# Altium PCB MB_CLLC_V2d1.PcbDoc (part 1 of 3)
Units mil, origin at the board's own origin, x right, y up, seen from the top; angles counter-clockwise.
Board outline 9000 x 7000 mil, 2 copper layers (Top Layer, Bottom Layer); 436 components, 223 nets, 1335 pads, 200 vias.
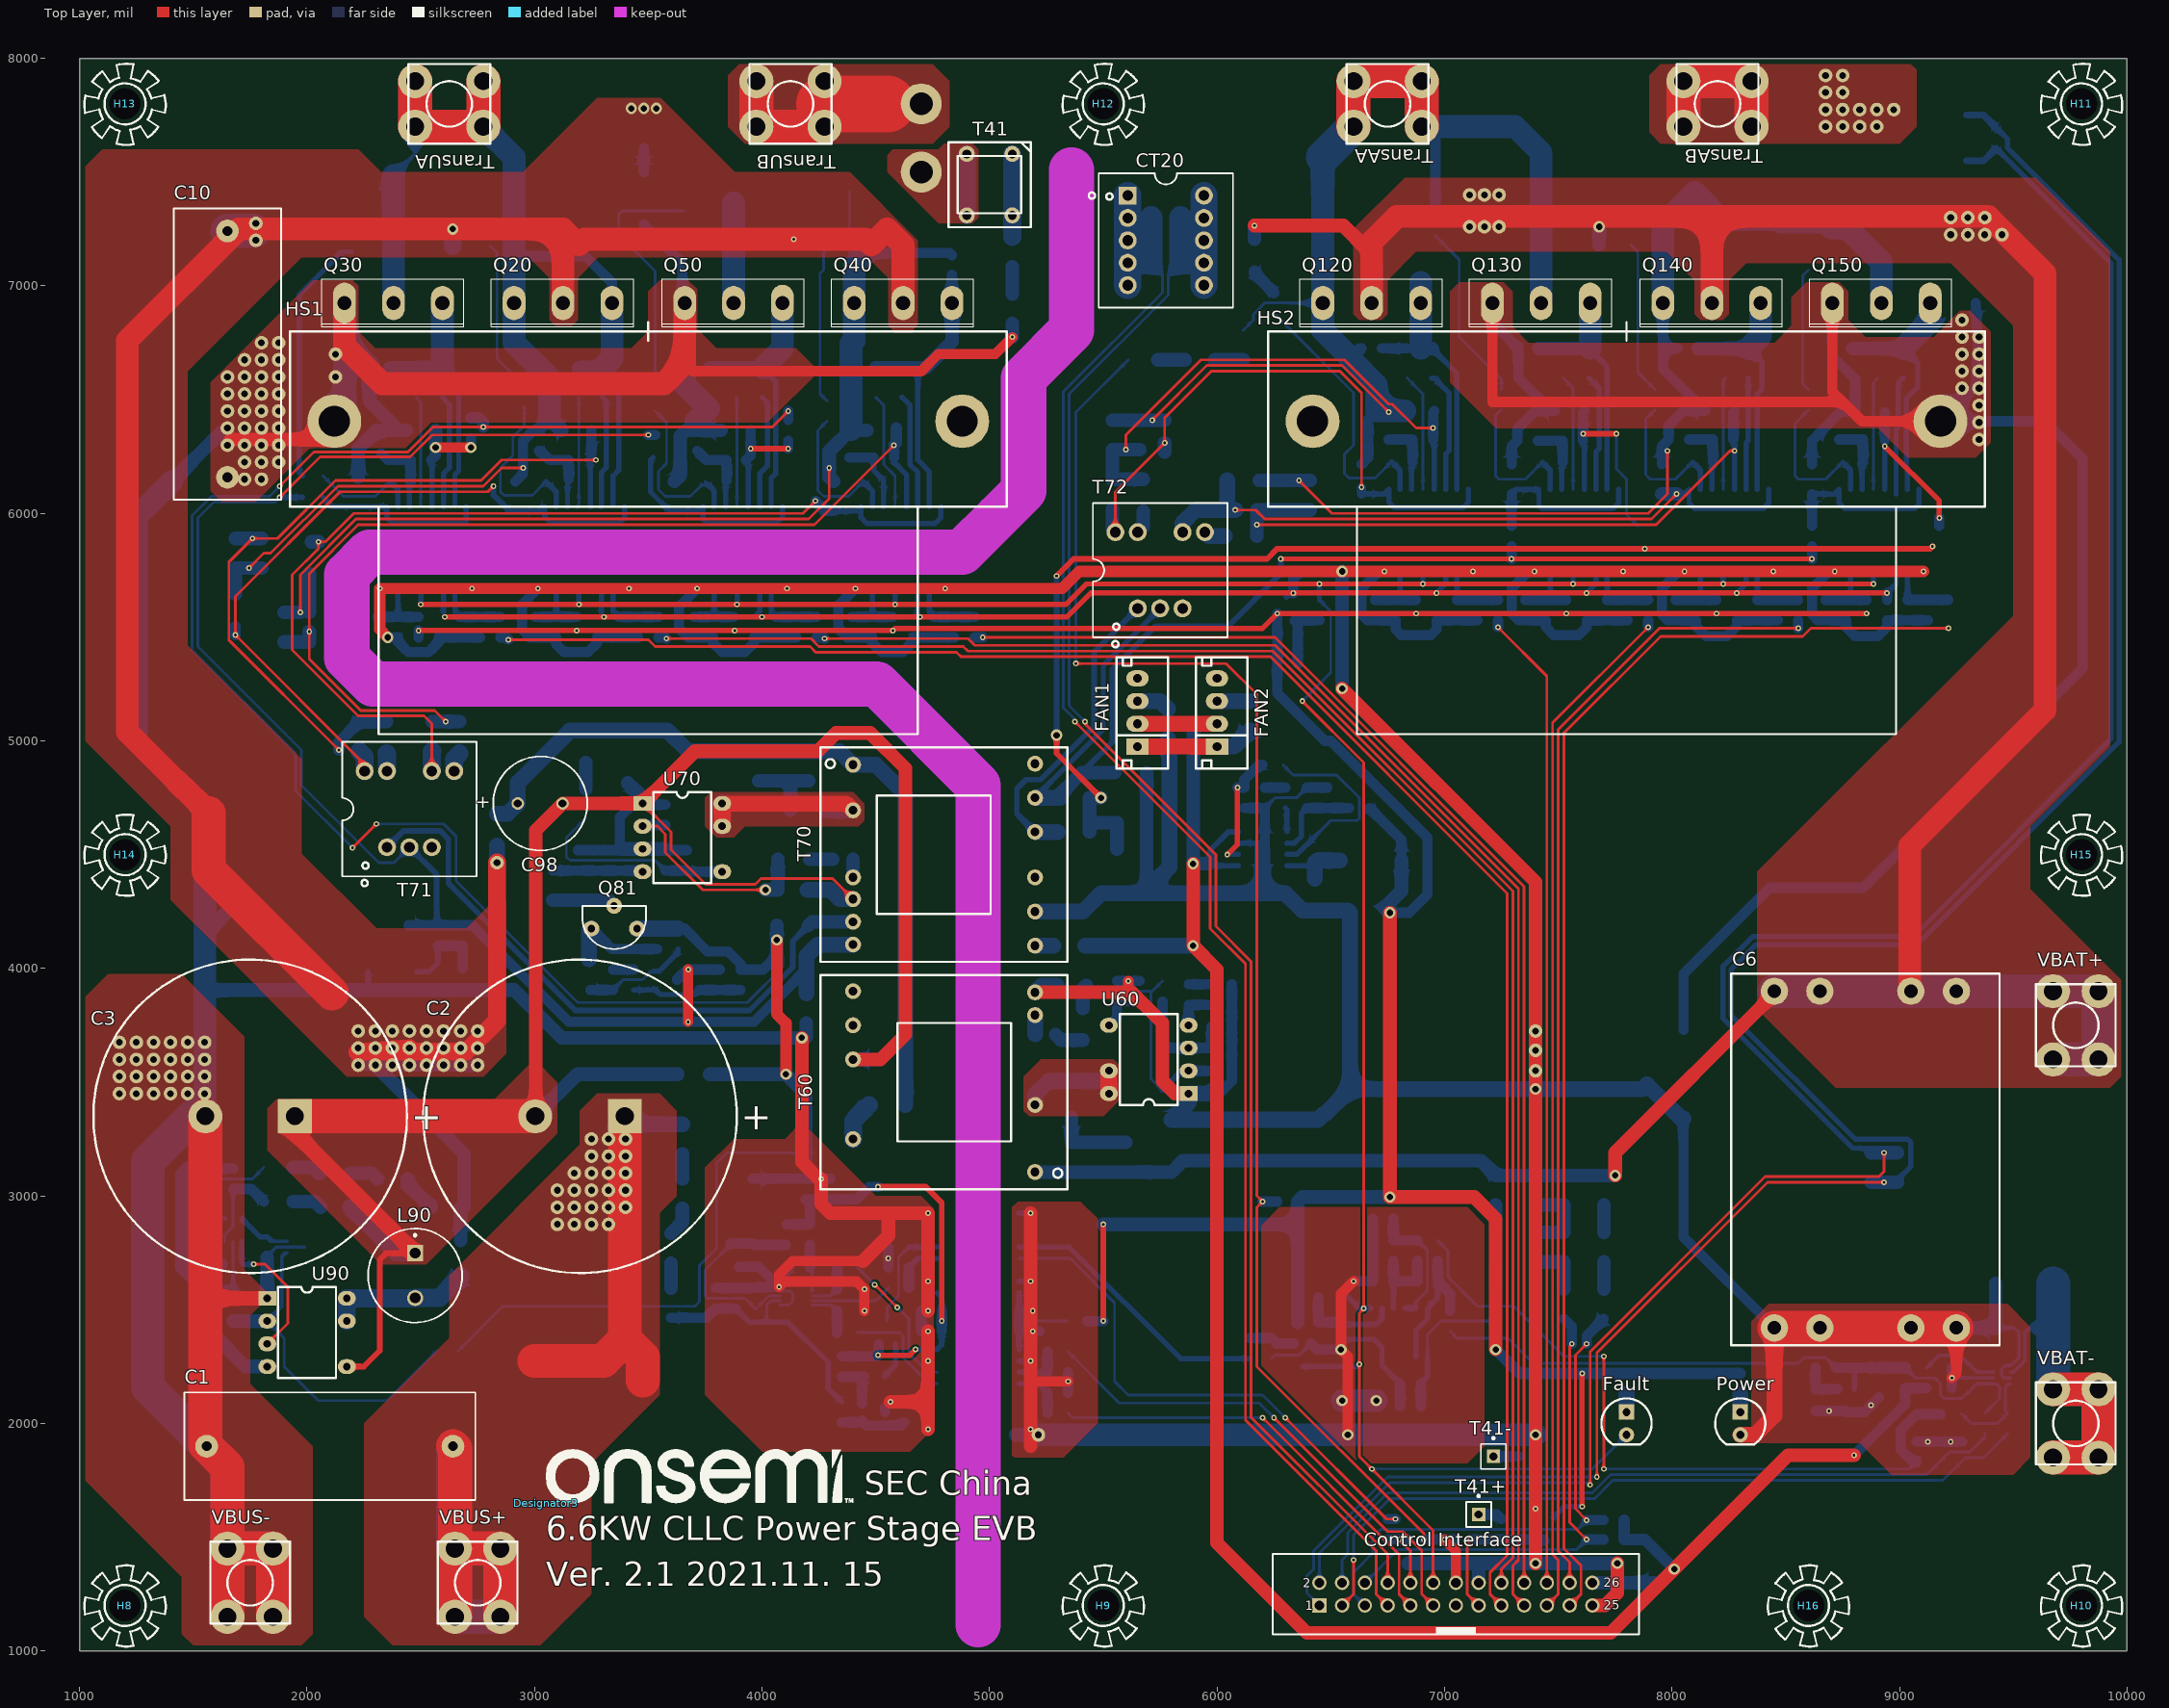
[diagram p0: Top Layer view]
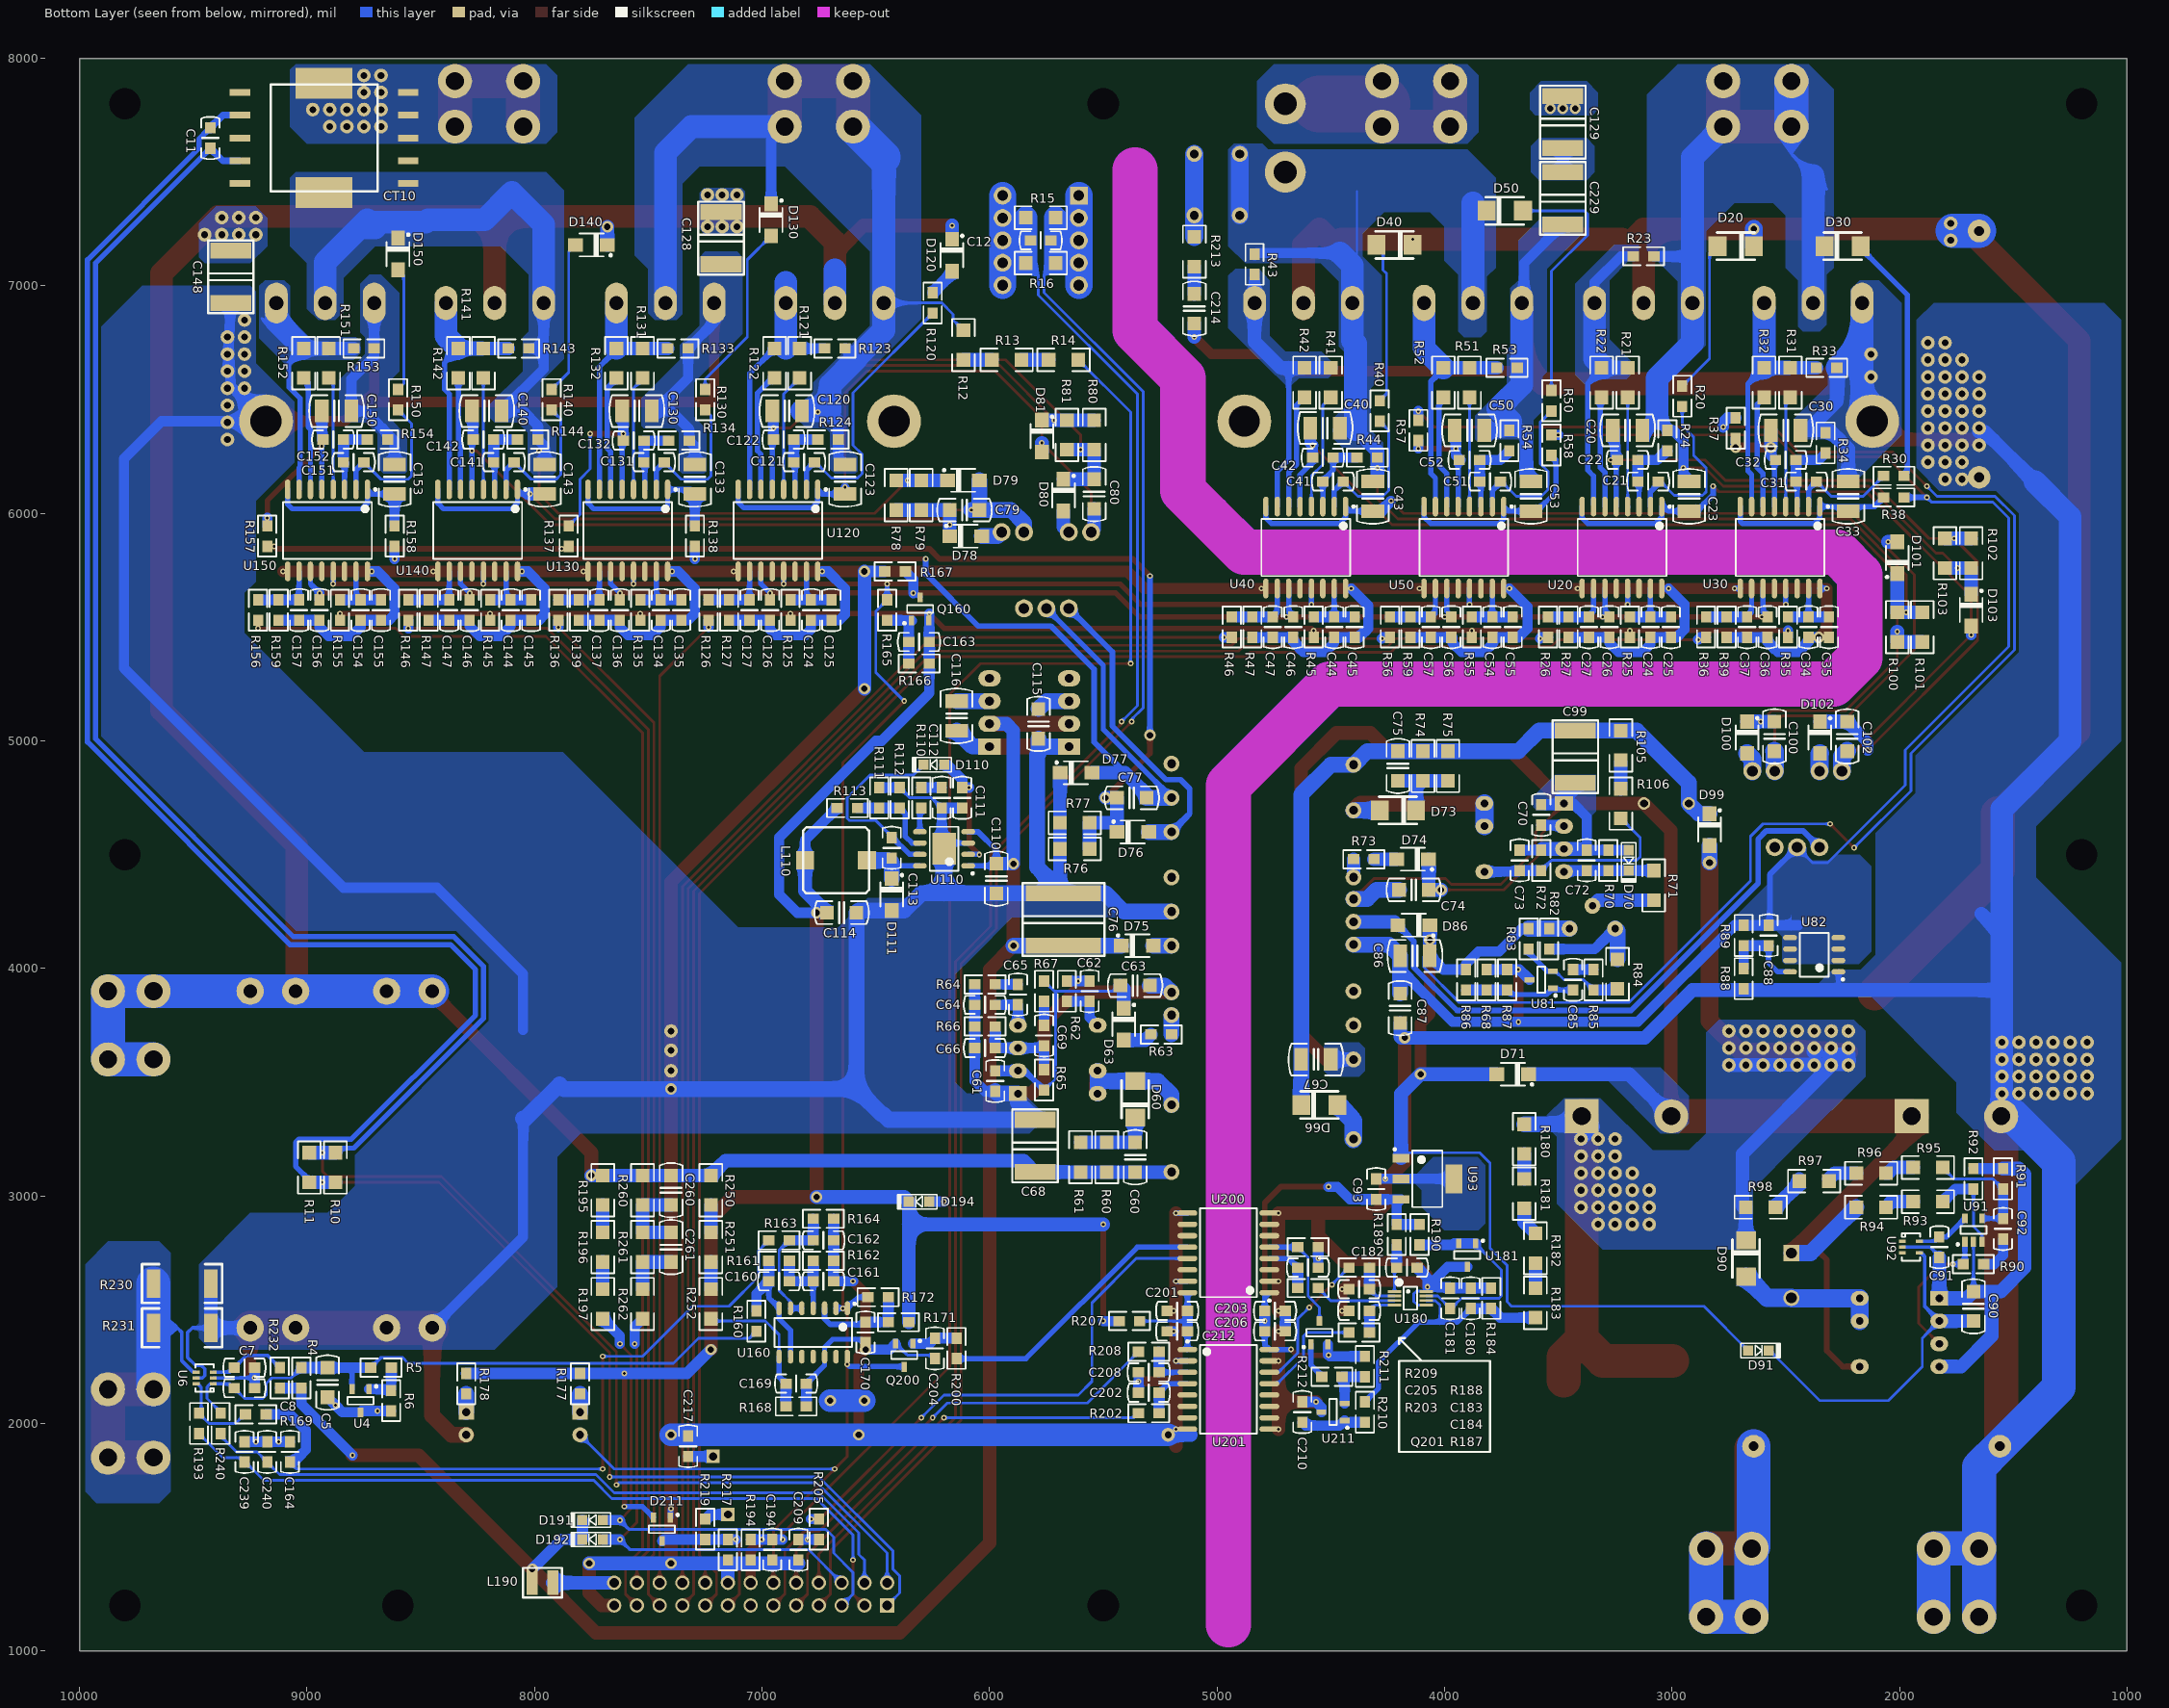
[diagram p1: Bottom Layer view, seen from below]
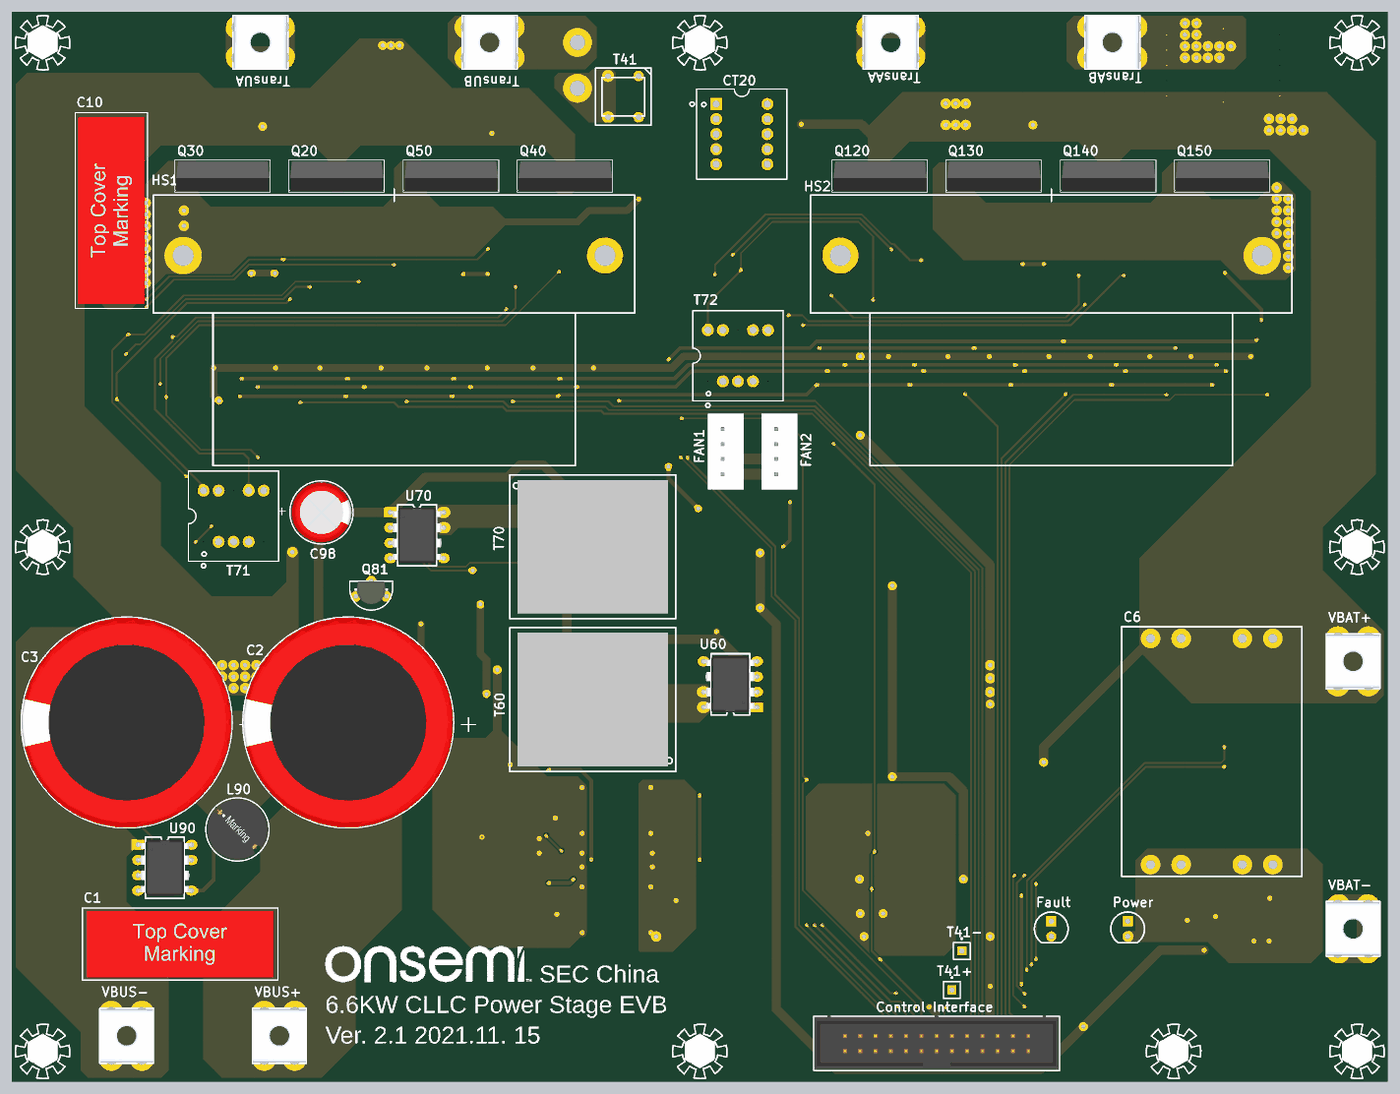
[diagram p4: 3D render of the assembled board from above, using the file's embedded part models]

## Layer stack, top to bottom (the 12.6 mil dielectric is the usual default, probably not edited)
Top Solder: solder mask 0.4, Solder Resist, Dk 3.5
Top Layer: signal copper 1.4
Dielectric 1: dielectric 12.6, FR-4, Dk 4.8
Bottom Layer: signal copper 1.4
Bottom Solder: solder mask 0.4, Solder Resist, Dk 3.5

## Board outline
1000,1000 1000,8000 10000,8000 10000,1000

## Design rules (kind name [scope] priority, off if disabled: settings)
Clearance [All] p1: gap=10 ignorepadtopadclearanceinfootprint=FALSE except(0: Arc-Hole Track-Hole SMDPad-Hole THPad-Hole Via-Hole Fill-Hole Poly-Hole Region-Hole Text-Hole)
PlaneConnect [All] p1: planeconnectstyle=Direct reliefexpansion=20 reliefentries=4 reliefconductorwidth=10 reliefairgap=10
PolygonConnect [All] p1: connectstyle=Direct reliefconductorwidth=10 reliefentries=4 polygonreliefangle="90 Angle" airgapwidth=10
RoutingVias [All] p1: holewidth=12 width=25 viastyle="Through Hole" minholewidth=12 minwidth=25 maxholewidth=28 maxwidth=50
SolderMaskExpansion [All] p1: expansion=4
Width [All] p1: maxlimit=250 minlimit=10 preferedwidth=45 minimp=50.000000 maximp=50.000000 favimp=50.000000
29 further rules are at their usual default settings.

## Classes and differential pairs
component class Sheet2_CLLC_V1d1: C1 C6 C7 C8 C10 C11 C12 C160 C161 C162 C163 C164 C169 C170 C180 C181 C182 C183 C184 C194 C201 C202 C203 C204 C205 C206 C208 C209 C210 C212 C214 C217 C239 C240 C260 C261 "Control Interface" CT10 CT20 D191 D192 D194 D211 Fault L190 Power Q160 Q180 Q200 Q201 R10 R11 R12 R13 R14 R15 R16 R160 R161 R162 R163 R164 R165 R166 R167 R168 R169 R171 R172 R177 R178 R180 R181 R182 R183 R184 R187 R188 R189 R190 R193 R194 R195 R196 R197 R200 R202 R203 R205 R207 R208 R209 R210 R211 R212 R213 R217 R219 R230 R231 R232 R240 R250 R251 R252 R260 R261 R262 T41 T41+ T41- U6 U160 U180 U181 U200 U201 U211 VBAT+ VBAT- VBUS+ VBUS-
component class Sheet1_CLLC_V1d1: C20 C21 C22 C23 C24 C25 C26 C27 C30 C31 C32 C33 C34 C35 C36 C37 C40 C41 C42 C43 C44 C45 C46 C47 C50 C51 C52 C53 C54 C55 C56 C57 C120 C121 C122 C123 C124 C125 C126 C127 C128 C129 C130 C131 C132 C133 C134 C135 C136 C137 C140 C141 C142 C143 C144 C145 C146 C147 C148 C150 C151 C152 C153 C154 C155 C156 C157 C229 D20 D30 D40 D50 D120 D130 D140 D150 Q20 Q30 Q40 Q50 Q120 Q130 Q140 Q150 R20 R21 R22 R23 R24 R25 R26 R27 R30 R31 R32 R33 R34 R35 R36 R37 R38 R39 R40 R41 R42 R43 R44 R45 R46 R47 R50 R51 R52 R53 R54 R55 R56 R57 R58 R59 R120 R121 R122 R123 R124 R125 R126 R127 R130 R131 R132 R133 R134 R135 R136 R137 R138 R139 R140 R141 R142 R143 R144 R145 R146 R147 R150 R151 R152 R153 R154 R155 R156 R157 R158 R159 TransAA TransAB TransUA TransUB U20 U30 U40 U50 U120 U130 U140 U150
component class Auxiliary_Power: C2 C3 C5 C60 C61 C62 C63 C64 C65 C66 C67 C68 C69 C70 C72 C73 C74 C75 C76 C77 C79 C80 C85 C86 C87 C88 C90 C91 C92 C93 C98 C99 C100 C102 C110 C111 C112 C113 C114 C115 C116 D60 D63 D66 D70 D71 D73 D74 D75 D76 D77 D78 D79 D80 D81 D86 D90 D91 D99 D100 D101 D102 D103 D110 D111 FAN1 FAN2 L90 L110 Q81 R4 R5 R6 R60 R61 R62 R63 R64 R65 R66 R67 R68 R70 R71 R72 R73 R74 R75 R76 R77 R78 R79 R80 R81 R82 R83 R84 R85 R86 R87 R88 R89 R90 R91 R92 R93 R94 R95 R96 R97 R98 R100 R101 R102 R103 R105 R106 R110 R111 R112 R113 T60 T70 T71 T72 U4 U60 U70 U81 U82 U90 U91 U92 U93 U110

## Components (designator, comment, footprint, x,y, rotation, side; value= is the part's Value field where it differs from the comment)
C1 "470nF, 1000V" L31_W11_H20_P27.5 2100,1900 r0 top locked
C2 "680uF/450V" WCAP-AI3H_35x57 3200,3350 r0 top locked
C3 "680uF/450V" WCAP-AI3H_35x57 1750,3350 r0 top locked
C5 "106" SMT_1206_CM 8910,2180 r90 bottom
C6 "30uF/800V" CAP-FILM_EZPE_41X30A 8850,3160 r270 top locked
C7 "104" SMT_0805_CM 9275,2245 r0 bottom
C8 "104" SMT_0805_CM 9275,2155 r0 bottom
C10 "470nF, 1000V" L31_W11_H20_P27.5 1650,6700 r90 top locked
C11 "101" SMT_0805_CM 9425,7650 r90 bottom
C12 "101" SMT_0805_CM 5775,7200 r180 bottom
C20 "226" SMT_1210 3195,6365 r180 bottom
C21 "101" SMT_0805_CM 3105,6140 r180 bottom
C22 "105" SMT_0805_CM 3195,6235 r180 bottom
C23 "226" SMT_1210 2925,6075 r90 bottom locked
C24 "104" SMT_0805_CM 3095,5500 r90 bottom
C25 "225" SMT_0805_CM 3005,5500 r90 bottom
C26 "101" SMT_0805_CM 3275,5500 r270 bottom
C27 "101" SMT_0805_CM 3365,5500 r90 bottom
C30 "226" SMT_1210 2500,6365 r180 bottom
C31 "101" SMT_0805_CM 2410,6140 r180 bottom
C32 "105" SMT_0805_CM 2500,6235 r180 bottom
C33 "226" SMT_1210 2225,6075 r90 bottom
C34 "104" SMT_0805_CM 2400,5500 r90 bottom
C35 "225" SMT_0805_CM 2310,5500 r90 bottom
C36 "101" SMT_0805_CM 2580,5500 r270 bottom
C37 "101" SMT_0805_CM 2670,5500 r90 bottom
C40 "226" SMT_1210 4525,6375 r180 bottom
C41 "101" SMT_0805_CM 4490,6140 r180 bottom
C42 "105" SMT_0805_CM 4535,6245 r180 bottom
C43 "226" SMT_1210 4315,6075 r90 bottom
C44 "104" SMT_0805_CM 4485,5500 r90 bottom
C45 "225" SMT_0805_CM 4395,5500 r90 bottom
C46 "101" SMT_0805_CM 4665,5500 r270 bottom
C47 "101" SMT_0805_CM 4755,5500 r90 bottom
C50 "226" SMT_1210 3890,6365 r180 bottom
C51 "101" SMT_0805_CM 3800,6140 r180 bottom
C52 "105" SMT_0805_CM 3890,6235 r180 bottom locked
C53 "226" SMT_1210 3620,6075 r90 bottom
C54 "104" SMT_0805_CM 3790,5500 r90 bottom
C55 "225" SMT_0805_CM 3700,5500 r90 bottom
C56 "101" SMT_0805_CM 3970,5500 r270 bottom
C57 "101" SMT_0805_CM 4060,5500 r90 bottom
C60 "222/630V" SMT_1206_CM 5360,3170 r270 bottom
C61 "104" SMT_0805_CM 5975,3505 r90 bottom
C62 "102" SMT_0805_CM 5560,3900 r270 bottom
C63 "104/1206" SMT_1206_CM 5360,3925 r0 bottom
C64 "471" SMT_0805_CM 6020,3840 r180 bottom
C65 "223" SMT_0805_CM 5875,3885 r270 bottom
C66 "102" SMT_0805_CM 6020,3650 r180 bottom
C67 "154" SMT_1210 4565,3600 r0 bottom
C68 "105/630V" CAP2220 5800,3220 r270 bottom
C69 "223" SMT_0805_CM 5760,3705 r270 bottom
C70 "104" SMT_0805_CM 3575,4675 r270 bottom
C72 "102" SMT_0805_CM 3375,4475 r270 bottom
C73 "102" SMT_0805_CM 3670,4475 r270 bottom
C74 "106" SMT_1206_CM 4135,4345 r180 bottom
C75 "222/630V" SMT_1206_CM 4205,4890 r90 bottom
C76 "25V/157" CAP2220_3 5675,4215 r90 bottom
C77 "106" SMT_1206_CM 5375,4750 r0 bottom
C79 "106" SMT_1206_CM 6110,6015 r0 bottom
C80 "106" SMT_1206_CM 5540,6085 r90 bottom
C85 "223" SMT_0805_CM 3435,3950 r90 bottom
C86 "226" SMT_1210 4130,4055 r180 bottom
C87 "106" SMT_1206_CM 4195,3825 r270 bottom
C88 "102" SMT_0805_CM 2575,4145 r270 bottom
C90 "106" SMT_1206_CM 1675,2515 r270 bottom
C91 "105" SMT_0805_CM 1825,2775 r90 bottom
C92 "104" SMT_0805_CM 1545,2855 r90 bottom
C93 "105" SMT_0805_CM 4300,3030 r270 bottom
C98 "NC" WCAP-ATG5_10x25 3025,4725 r180 top locked
C99 "105/630V" CAP2220 3425,4930 r90 bottom locked
C100 "475" SMT_1206_CM 2550,5020 r90 bottom
C102 "475" SMT_1206_CM 2230,5020 r90 bottom
C110 "106" SMT_1206_CM 5970,4395 r90 bottom
C111 "104" SMT_0805_CM 6120,4750 r90 bottom
C112 "222" SMT_0805_CM 6210,4750 r90 bottom
C113 "104" SMT_0805_CM 6430,4530 r270 bottom
C114 "106" SMT_1206_CM 6650,4245 r0 bottom
C115 "106" SMT_1206_CM 5785,5075 r90 bottom
C116 "226" SMT_1210 6145,5110 r90 bottom
C120 "226" SMT_1210 6890,6450 r180 bottom
C121 "101" SMT_0805_CM 6815,6225 r180 bottom
C122 "105" SMT_0805_CM 6905,6325 r180 bottom
C123 "226" SMT_1210 6635,6150 r90 bottom locked
C124 "104" SMT_0805_CM 6785,5575 r90 bottom
C125 "225" SMT_0805_CM 6695,5575 r90 bottom
C126 "101" SMT_0805_CM 6965,5575 r270 bottom
C127 "101" SMT_0805_CM 7055,5575 r90 bottom
C128 "105/630V" CAP2220 7180,7210 r90 bottom
C129 "105/630V" CAP2220 3480,7720 r90 bottom
C130 "226" SMT_1210 7550,6450 r180 bottom
C131 "101" SMT_0805_CM 7475,6225 r180 bottom
C132 "105" SMT_0805_CM 7564,6320 r180 bottom
C133 "226" SMT_1210 7295,6150 r90 bottom
C134 "104" SMT_0805_CM 7445,5575 r90 bottom
C135 "225" SMT_0805_CM 7355,5575 r90 bottom
C136 "101" SMT_0805_CM 7625,5575 r270 bottom
C137 "101" SMT_0805_CM 7715,5575 r90 bottom
C140 "226" SMT_1210 8210,6450 r180 bottom
C141 "101" SMT_0805_CM 8135,6225 r180 bottom
C142 "105" SMT_0805_CM 8225,6325 r180 bottom
C143 "226" SMT_1210 7955,6150 r90 bottom
C144 "104" SMT_0805_CM 8105,5575 r90 bottom
C145 "225" SMT_0805_CM 8015,5575 r90 bottom
C146 "101" SMT_0805_CM 8285,5575 r270 bottom
C147 "101" SMT_0805_CM 8375,5575 r90 bottom
C148 "105/630V" CAP2220 9335,7040 r90 bottom
C150 "226" SMT_1210 8870,6450 r180 bottom
C151 "101" SMT_0805_CM 8795,6225 r180 bottom
C152 "105" SMT_0805_CM 8885,6325 r180 bottom
C153 "226" SMT_1210 8615,6150 r90 bottom locked
C154 "104" SMT_0805_CM 8765,5575 r90 bottom
C155 "225" SMT_0805_CM 8675,5575 r90 bottom
C156 "101" SMT_0805_CM 8945,5575 r270 bottom
C157 "101" SMT_0805_CM 9035,5575 r90 bottom
C160 "104" SMT_0805_CM 6925,2625 r0 bottom
C161 "104" SMT_0805_CM 6730,2625 r0 bottom
C162 "104" SMT_0805_CM 6730,2805 r0 bottom
C163 "471" SMT_0805_CM 6310,5435 r180 bottom
C164 "102" SMT_0805_CM 9075,1875 r270 bottom
C169 "102" SMT_0805_CM 6850,2175 r0 bottom
C170 "104" SMT_0805_CM 6545,2400 r90 bottom
C180 "101" SMT_0805_CM 3885,2550 r270 bottom
C181 "104" SMT_0805_CM 3975,2550 r270 bottom
C182 "104" SMT_0805_CM 4165,2685 r0 bottom
C183 "101" SMT_0805_CM 4375,2590 r180 bottom
C184 "101" SMT_0805_CM 4375,2495 r180 bottom
C194 "NC" SMT_0805_CM 6955,1445 r90 bottom
C201 "105" SMT_0805_CM 5175,2495 r180 bottom
C202 "101" SMT_0805_CM 5300,2135 r180 bottom
C203 "104" SMT_0805_CM 4745,2495 r0 bottom
C204 "102" SMT_0805_CM 6240,2330 r90 bottom
C205 "101" SMT_0805_CM 4600,2685 r0 bottom
C206 "105" SMT_0805_CM 4745,2405 r0 bottom
C208 "101" SMT_0805_CM 5300,2225 r180 bottom
C209 "NC" SMT_0805_CM 6840,1445 r90 bottom
C210 "101" SMT_0805_CM 4625,2050 r270 bottom
C212 "104" SMT_0805_CM 5175,2405 r180 bottom
C214 "222/630V" SMT_1206_CM 5100,6900 r90 bottom
C217 "104" SMT_0805_CM 7325,1900 r270 bottom
C229 "105/630V" CAP2220 3480,7385 r90 bottom
C239 "102" SMT_0805_CM 9275,1875 r270 bottom
C240 "102" SMT_0805_CM 9175,1875 r270 bottom
C260 "222/630V" SMT_1206_CM 7400,3025 r90 bottom
C261 "222/630V" SMT_1206_CM 7400,2775 r90 bottom
"Control Interface" "61202621621" 61202621621 7050,1250 r0 top locked
CT10 "WE_750316796" CT_EE13 8925,7650 r180 bottom locked
CT20 "WE_750344930" Trans_EE13_6_6_10Pin_V#1 5775,7200 r0 top locked
D20 "NRVUS2MA" DO-214AC(SMA) 2720,7175 r180 bottom
D30 "NRVUS2MA" DO-214AC(SMA) 2250,7175 r0 bottom
D40 "NRVUS2MA" DO-214AC(SMA) 4220,7180 r180 bottom locked
D50 "NRVUS2MA" DO-214AC(SMA) 3735,7330 r0 bottom
D60 "NRVA4007T3G" DO-214AC(SMA) 5360,3425 r270 bottom
D63 "NRVHPRS1BFA" SOD-123FL 5410,3755 r270 bottom
D66 "NRVUS2MA" DO-214AC(SMA) 4550,3400 r0 bottom
D70 "BAS16H" SOD-323M 3190,4520 r270 bottom
D71 "NRVUS1JFA" SOD-123FL 3700,3535 r0 bottom
D73 "NRVA4007T3G" DO-214AC(SMA) 4205,4695 r180 bottom
D74 "NRVHPRS1BFA" SOD-123FL 4140,4480 r0 bottom
D75 "NRVBSS36FA" SOD-123FL 5350,4100 r180 bottom
D76 "NRVBS215FA" SOD-123FL 5370,4600 r180 bottom
D77 "MMSZ4V7T1G" SOD-123FL 5620,4860 r180 bottom
D78 "NRVBS215FA" SOD-123FL 6105,5900 r180 bottom
D79 "MMSZ4V7T1G" SOD-123FL 6115,6145 r180 bottom
D80 "NRVBS215FA" SOD-123FL 5675,6080 r270 bottom
D81 "MMSZ4V7T1G" SOD-123FL 5770,6340 r270 bottom
D86 "NRVBS215FA" SOD-123FL 4135,4190 r0 bottom
D90 "NRVUS2MA" DO-214AC(SMA) 2675,2725 r90 bottom
D91 "BAS16H" SOD-323M 2665,2320 r180 bottom
D99 "NRVUS1JFA" SOD-123FL 2835,4610 r270 bottom
D100 "NRVBS215FA" SOD-123FL 2670,5015 r270 bottom
D101 "MMSZ4V7T1G" SOD-123FL 2010,5805 r90 bottom
D102 "NRVBS215FA" SOD-123FL 2350,5015 r270 bottom
D103 "MMSZ4V7T1G" SOD-123FL 1685,5575 r270 bottom
D110 "BAS16H" SOD-323M 6200,4895 r0 bottom
D111 "NRVB120VLSFT1G" SOD-123FL 6430,4325 r270 bottom
D120 "NRVUS1JFA" SOD-123FL 6165,7135 r270 bottom
D130 "NRVUS1JFA" SOD-123FL 6960,7290 r270 bottom
D140 "NRVUS1JFA" SOD-123FL 7750,7180 r0 bottom
D150 "NRVUS1JFA" SOD-123FL 8600,7140 r270 bottom
D191 "BAS16H" SOD-323M 7700,1575 r0 bottom
D192 "BAS16H" SOD-323M 7700,1490 r0 bottom
D194 "BAS16H" SOD-323M 6265,2975 r0 bottom
D211 "BAT54S" SOT-23-3L 7440,1535 r270 bottom
Designator3 "Comment" Logo 3050,1650 r0 top
FAN1 "" XH-4A 5650,4975 r90 top locked
FAN2 "" XH-4A 6000,4975 r90 top locked
Fault "Red" "LED 5MM-R" 7800,2000 r270 top locked
H8 "Comment" HOLE3.5-2 1200,1200 r0 top locked
H9 "Comment" HOLE3.5-2 5500,1200 r0 top locked
H10 "Comment" HOLE3.5-2 9800,1200 r0 top locked
H11 "Comment" HOLE3.5-2 9800,7800 r0 top locked
H12 "Comment" HOLE3.5-2 5500,7800 r0 top
H13 "Comment" HOLE3.5-2 1200,7800 r0 top locked
H14 "Comment" HOLE3.5-2 1200,4500 r0 top locked
H15 "Comment" HOLE3.5-2 9800,4500 r0 top locked
H16 "Comment" HOLE3.5-2 8600,1200 r0 top locked
HS1 "Comment" Heatsink_80x60x20_with_25mm_FAN 3500,6800 r180 top locked
HS2 "Comment" Heatsink_80x60x20_with_25mm_FAN 7800,6800 r180 top locked
L90 "2200 uH, 0.48 A" WE-TI_1014_Standard 2475,2650 r270 top
L110 "22uH" INDUCTOR-7*7*3.5 6675,4475 r0 bottom
L190 "100uH" Bead_1210 7965,1300 r0 bottom
Power "Green" "LED 5MM-R" 8300,2000 r270 top locked
Q20 "NVHL040N120SC1" TO247#1 3125,6925 r180 top locked
Q30 "NVHL040N120SC1" TO247#2 2380,6925 r180 top locked
Q40 "NVHL040N120SC1" TO247#1 4620,6925 r180 top locked
Q50 "NVHL040N120SC1" TO247#3 3875,6925 r180 top locked
Q81 "FQN1N60CTA" TO92a 3350,4225 r180 top
Q120 "NVHL020N090SC1" TO247#1 6680,6925 r180 top locked
Q130 "NVHL020N090SC1" TO247#4 7425,6925 r180 top locked
Q140 "NVHL020N090SC1" TO247#1 8175,6925 r180 top locked
Q150 "NVHL020N090SC1" TO247#4 8920,6925 r180 top locked
Q160 "SMMBT2907ALT1G" SOT-23-3L 6305,5580 r90 bottom
Q200 "SMMBT4401LT1G" SOT-23-3L 6375,2300 r270 bottom
Q201 "SMMBT2907ALT1G" SOT-23-3L 4550,2398.82 r90 bottom
R4 "2.2K" SMT_0805_RM 9025,2200 r90 bottom
R5 "6.65K" SMT_0805_RM 8675,2245 r180 bottom
R6 "4.75K" SMT_0805_RM 8630,2100 r270 bottom
R10 "100" SMT_1206_RM 8875,3125 r270 bottom
R11 "100" SMT_1206_RM 8990,3125 r270 bottom
R12 "150K" SMT_1206_RM 6115,6740 r90 bottom
R13 "150K" SMT_1206_RM 5925,6675 r0 bottom
R14 "150K" SMT_1206_RM 5675,6675 r0 bottom
R15 "150" SMT_1206_RM 5775,7300 r180 bottom
R16 "150" SMT_1206_RM 5775,7100 r180 bottom
R20 "1K" SMT_0805_RM 2955,6515 r270 bottom
R21 "4.7" SMT_1206_RM 3195,6575 r90 bottom
R22 "4.7" SMT_1206_RM 3310,6575 r90 bottom locked
R23 "10K" SMT_0805_RM 3125,7130 r0 bottom locked
R24 "2.2" SMT_0805_RM 3020,6320 r270 bottom
R25 "4.7" SMT_0805_RM 3185,5500 r90 bottom
R26 "100" SMT_0805_RM 3545,5500 r270 bottom
R27 "2.2K" SMT_0805_RM 3455,5500 r270 bottom
R30 "1K" SMT_0805_RM 2025,6165 r0 bottom
R31 "4.7" SMT_1206_RM 2480,6575 r90 bottom
R32 "4.7" SMT_1206_RM 2595,6575 r90 bottom locked
R33 "10K" SMT_0805_RM 2320,6640 r0 bottom
R34 "2.2" SMT_0805_RM 2325,6310 r270 bottom
R35 "4.7" SMT_0805_RM 2490,5500 r90 bottom
R36 "100" SMT_0805_RM 2850,5500 r270 bottom
R37 "4.7" SMT_0805_RM 2720,6375 r270 bottom
R38 "4.7" SMT_0805_RM 2025,6070 r180 bottom
R39 "2.2K" SMT_0805_RM 2760,5500 r270 bottom
R40 "1K" SMT_0805_RM 4285,6450 r270 bottom
R41 "4.7" SMT_1206_RM 4500,6575 r90 bottom
R42 "4.7" SMT_1206_RM 4615,6575 r90 bottom
R43 "10K" SMT_0805_RM 4835,7095 r270 bottom
R44 "2.2" SMT_0805_RM 4340,6245 r0 bottom
R45 "4.7" SMT_0805_RM 4575,5500 r90 bottom
R46 "100" SMT_0805_RM 4935,5500 r270 bottom
R47 "2.2K" SMT_0805_RM 4845,5500 r270 bottom
R50 "1K" SMT_0805_RM 3530,6495 r270 bottom
R51 "4.7" SMT_1206_RM 3890,6575 r90 bottom
R52 "4.7" SMT_1206_RM 4005,6575 r90 bottom
R53 "10K" SMT_0805_RM 3725,6640 r0 bottom
R54 "2.2" SMT_0805_RM 3715,6320 r270 bottom
R55 "4.7" SMT_0805_RM 3880,5500 r90 bottom
R56 "100" SMT_0805_RM 4240,5500 r270 bottom
R57 "4.7" SMT_0805_RM 4115,6365 r270 bottom
R58 "4.7" SMT_0805_RM 3530,6300 r90 bottom
R59 "2.2K" SMT_0805_RM 4150,5500 r270 bottom
R60 "470K" SMT_1206_RM 5485,3170 r270 bottom
R61 "470K" SMT_1206_RM 5600,3170 r270 bottom
R62 "100K" SMT_0805_RM 5660,3900 r90 bottom
R63 "2.2" SMT_0805_RM 5245,3710 r0 bottom
R64 "10K" SMT_0805_RM 6020,3930 r0 bottom
R65 "220K" SMT_0805_RM 5760,3510 r90 bottom
R66 "43K" SMT_0805_RM 6020,3745 r0 bottom
R67 "43K" SMT_0805_RM 5760,3900 r270 bottom
R68 "56K" SMT_0805_RM 3815,3950 r90 bottom
R70 "100K" SMT_0805_RM 3280,4475 r90 bottom
R71 "47K" SMT_1206_RM 3080,4365 r90 bottom
R72 "20K" SMT_0805_RM 3575,4475 r90 bottom
R73 "2.2" SMT_0805_RM 4355,4480 r180 bottom
R74 "470K" SMT_1206_RM 4095,4890 r90 bottom
R75 "470K" SMT_1206_RM 3985,4890 r90 bottom
R76 "2.2K" SMT_1206_RM 5625,4525 r180 bottom
R77 "2.2K" SMT_1206_RM 5625,4640 r180 bottom
R78 "2.2K" SMT_1206_RM 6410,6080 r270 bottom
R79 "2.2K" SMT_1206_RM 6300,6080 r270 bottom
R80 "2.2K" SMT_1206_RM 5540,6345 r270 bottom
R81 "2.2K" SMT_1206_RM 5660,6345 r270 bottom
R82 "20K" SMT_0805_RM 3540,4130 r90 bottom
R83 "10K" SMT_0805_RM 3630,4130 r90 bottom
R84 "47K" SMT_1206_RM 3240,3975 r270 bottom
R85 "4.7K" SMT_0805_RM 3345,3950 r90 bottom
R86 "39K" SMT_0805_RM 3905,3950 r270 bottom
R87 "4.7K" SMT_0805_RM 3725,3950 r90 bottom
R88 "4.7K" SMT_0805_RM 2685,3955 r90 bottom
R89 "4.7K" SMT_0805_RM 2685,4145 r90 bottom
R90 "100K" SMT_0805_RM 1675,2700 r180 bottom
R91 "12.7K" SMT_0805_RM 1545,3075 r90 bottom
R92 "12.7K" SMT_0805_RM 1675,3075 r90 bottom
R93 "1M" SMT_1206_RM 1875,2975 r0 bottom
R94 "1M" SMT_1206_RM 2125,2950 r0 bottom
R95 "1M" SMT_1206_RM 1875,3125 r0 bottom
R96 "1M" SMT_1206_RM 2125,3100 r0 bottom
R97 "1M" SMT_1206_RM 2375,3065 r0 bottom
R98 "1M" SMT_1206_RM 2610,2950 r0 bottom
R100 "3.9K" SMT_1206_RM 2010,5500 r270 bottom
R101 "3.9K" SMT_1206_RM 1900,5500 r270 bottom
R102 "3.9K" SMT_1206_RM 1685,5825 r90 bottom
R103 "3.9K" SMT_1206_RM 1800,5825 r90 bottom
R105 "1M" SMT_1206_RM 3225,4980 r90 bottom
R106 "1M" SMT_1206_RM 3225,4725 r90 bottom
R110 "10K" SMT_0805_RM 6300,4750 r90 bottom
R111 "100" SMT_0805_RM 6485,4750 r90 bottom
R112 "2.2K" SMT_0805_RM 6395,4750 r90 bottom
R113 "300" SMT_0805_RM 6625,4705 r180 bottom
R120 "1K" SMT_0805_RM 6250,6925 r270 bottom
R121 "4.7" SMT_1206_RM 6835,6660 r90 bottom
R122 "4.7" SMT_1206_RM 6945,6660 r90 bottom
R123 "10K" SMT_0805_RM 6680,6725 r0 bottom
R124 "2.2" SMT_0805_RM 6710,6325 r0 bottom
R125 "4.7" SMT_0805_RM 6875,5575 r90 bottom
R126 "100" SMT_0805_RM 7235,5575 r270 bottom
R127 "2.2K" SMT_0805_RM 7145,5575 r270 bottom
R130 "1K" SMT_0805_RM 7250,6500 r270 bottom
R131 "4.7" SMT_1206_RM 7525,6660 r90 bottom
R132 "4.7" SMT_1206_RM 7640,6660 r90 bottom
R133 "10K" SMT_0805_RM 7370,6725 r0 bottom
R134 "2.2" SMT_0805_RM 7365,6320 r0 bottom
R135 "4.7" SMT_0805_RM 7535,5575 r90 bottom
R136 "100" SMT_0805_RM 7895,5575 r270 bottom
R137 "4.7" SMT_0805_RM 7850,5900 r90 bottom
R138 "4.7" SMT_0805_RM 7295,5900 r270 bottom
R139 "2.2K" SMT_0805_RM 7805,5575 r270 bottom
R140 "1K" SMT_0805_RM 7925,6500 r270 bottom
R141 "4.7" SMT_1206_RM 8225,6660 r90 bottom
R142 "4.7" SMT_1206_RM 8335,6660 r90 bottom
R143 "10K" SMT_0805_RM 8070,6725 r0 bottom
R144 "2.2" SMT_0805_RM 8030,6325 r0 bottom
R145 "4.7" SMT_0805_RM 8195,5575 r90 bottom
R146 "100" SMT_0805_RM 8555,5575 r270 bottom
R147 "2.2K" SMT_0805_RM 8465,5575 r270 bottom
R150 "1K" SMT_0805_RM 8600,6500 r270 bottom
R151 "4.7" SMT_1206_RM 8905,6660 r90 bottom
R152 "4.7" SMT_1206_RM 9015,6660 r90 bottom
R153 "10K" SMT_0805_RM 8750,6725 r0 bottom
R154 "2.2" SMT_0805_RM 8690,6325 r0 bottom
R155 "4.7" SMT_0805_RM 8855,5575 r90 bottom
R156 "100" SMT_0805_RM 9215,5575 r270 bottom
R157 "4.7" SMT_0805_RM 9175,5900 r90 bottom
R158 "4.7" SMT_0805_RM 8615,5900 r270 bottom
R159 "2.2K" SMT_0805_RM 9125,5575 r270 bottom
R160 "27K" SMT_0805_RM 7025,2450 r90 bottom
R161 "10K" SMT_0805_RM 6925,2715 r180 bottom
R162 "1.8K" SMT_0805_RM 6730,2715 r180 bottom
R163 "10K" SMT_0805_RM 6925,2805 r180 bottom
R164 "4.75K" SMT_0805_RM 6730,2900 r180 bottom
R165 "4.7K" SMT_0805_RM 6450,5575 r90 bottom
R166 "2.2K" SMT_0805_RM 6310,5340 r0 bottom
R167 "1K" SMT_0805_RM 6415,5745 r0 bottom
R168 "11.5K" SMT_0805_RM 6850,2075 r180 bottom
R169 "12K" SMT_0805_RM 9225,2040 r180 bottom
R171 "10" SMT_0805_RM 6400,2445 r0 bottom
R172 "2.2K" SMT_0805_RM 6490,2555 r0 bottom
R177 "330" SMT_0805_RM 7800,2175 r90 bottom
R178 "330" SMT_0805_RM 8300,2175 r270 bottom
R180 "1M" SMT_1206_RM 3650,3250 r90 bottom
R181 "1M" SMT_1206_RM 3650,3010 r90 bottom
R182 "1M" SMT_1206_RM 3600,2770 r90 bottom
R183 "1M" SMT_1206_RM 3600,2530 r90 bottom
R184 "12.7K" SMT_0805_RM 3795,2550 r90 bottom
R187 "100" SMT_0805_RM 4375,2400 r0 bottom
R188 "100" SMT_0805_RM 4375,2685 r0 bottom
R189 "10" SMT_0805_RM 4210,2830 r90 bottom
R190 "470" SMT_0805_RM 4110,2830 r270 bottom
R193 "2.2K" SMT_0805_RM 9475,2000 r270 bottom
R194 "NC" SMT_0805_RM 7050,1445 r270 bottom
R195 "1M" SMT_1206_RM 7700,3025 r90 bottom
R196 "1M" SMT_1206_RM 7700,2775 r90 bottom
R197 "1M" SMT_1206_RM 7700,2525 r90 bottom
R200 "1K" SMT_0805_RM 6145,2330 r90 bottom
R202 "100" SMT_0805_RM 5300,2045 r0 bottom
R203 "100" SMT_0805_RM 4600,2595 r0 bottom
R205 "100" SMT_0805_RM 6750,1535 r270 bottom
R207 "10" SMT_0805_RM 5385,2450 r0 bottom
R208 "100" SMT_0805_RM 5300,2315 r0 bottom
R209 "4.7K" SMT_0805_RM 4600,2775 r180 bottom
R210 "10K" SMT_0805_RM 4350,2050 r90 bottom
R211 "1K" SMT_0805_RM 4350,2250 r270 bottom
R212 "10K" SMT_0805_RM 4495,2205 r0 bottom
R213 "1K" SMT_1206_RM 5100,7150 r90 bottom
R217 "10K" SMT_0805_RM 7150,1445 r270 bottom
R219 "1K" SMT_0805_RM 7250,1535 r270 bottom
R230 "2mR" SMT_2512_R 9675,2615 r0 bottom
R231 "2mR" SMT_2512_R 9675,2420 r0 bottom
R232 "10" SMT_0805_RM 9120,2200 r90 bottom
R240 "2.2K" SMT_0805_RM 9380,2000 r270 bottom
R250 "1M" SMT_1206_RM 7225,3025 r90 bottom
R251 "1M" SMT_1206_RM 7225,2775 r90 bottom
R252 "1M" SMT_1206_RM 7225,2525 r90 bottom
R260 "3M" SMT_1206_RM 7525,3025 r90 bottom
R261 "3M" SMT_1206_RM 7525,2775 r90 bottom
R262 "3M" SMT_1206_RM 7525,2525 r90 bottom
T41 "EE8" EE8 5000,7445 r270 top locked
T41+ "" PIN1 7150,1600 r0 top
T41- "" PIN1 7215,1855 r0 top
T60 "PQ2016" Trans_PQ2016_14P#1 4800,3500 r180 top locked
T70 "PQ2016" Trans_PQ2016_14P#2 4800,4500 r0 top locked
T71 "EE13" Trans_EE13_6_6_10Pin_V#2 2450,4700 r90 top locked
T72 "EE13" Trans_EE13_6_6_10Pin_V#2 5750,5750 r90 top locked
TransAA "" TermL 6750,7800 r90 top
TransAB "" TermL 8200,7800 r90 top
TransUA "" TermL 2625,7800 r90 top
TransUB "" TermL 4125,7800 r90 top
U4 "SC431AVSNT1G" SOT-23-3L 8765,2100 r270 bottom
U6 "NCV210RSQT2G" SC70-6 9450,2200 r90 bottom
U20 "NCV57000DWR2G" SOP16W 3220,5850 r270 bottom locked
U30 "NCV57000DWR2G" SOP16W 2525,5850 r270 bottom locked
U40 "NCV57000DWR2G" SOP16W 4610,5850 r270 bottom locked
U50 "NCV57000DWR2G" SOP16W 3915,5850 r270 bottom locked
U60 "FSL538APG" DIP7 5700,3600 r180 top locked
U70 "FSL538APG" DIP7 3650,4575 r0 top locked
U81 "SC431AVSNT1G" SOT-23-3L 3575,3950 r0 bottom
U82 "NCV431AIDR2G" Sop8 2375,4060 r0 bottom locked
U90 "FSL4110LRN" DIP7 2000,2400 r0 top
U91 "NCV2003SN2T1G" SOT-23-5L 1675,2850 r90 bottom
U92 "NCV8715SQ33T2G" SC70-5 1950,2775 r270 bottom
U93 "NCV4274CST33T3G" SOT-223 4075,3075 r180 bottom locked
U110 "NCV890100PDR2G" SOIC8E 6200,4526 r0 bottom locked
U120 "NCV57000DWR2G" SOP16W 6930,5925 r270 bottom locked
U130 "NCV57000DWR2G" SOP16W 7590,5925 r270 bottom locked
U140 "NCV57000DWR2G" SOP16W 8250,5925 r270 bottom locked
U150 "NCV57000DWR2G" SOP16W 8910,5925 r270 bottom locked
U160 "NCV2901DR2G" SOP14 6800,2400 r270 bottom locked
U180 "NCD98010XMXTAG" SSOP8 4150,2550 r180 bottom locked
U181 "SC431AVSNT1G" SOT-23-3L 3900,2740 r270 bottom
U200 "NCID9401" SOP16W 4950,2750 r0 bottom locked
U201 "NCID9401" SOP16W 4950,2150 r180 bottom locked
U211 "SC431AVSNT1G" SOT-23-3L 4490,2050 r0 bottom
VBAT+ "" TermL 9775,3750 r0 top
VBAT- "" TermL 9775,2000 r0 top
VBUS+ "" TermL 2750,1300 r0 top
VBUS- "" TermL 1750,1300 r0 top

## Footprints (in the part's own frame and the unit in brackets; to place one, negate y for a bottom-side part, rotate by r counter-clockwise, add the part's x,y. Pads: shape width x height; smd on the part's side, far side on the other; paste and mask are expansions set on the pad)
61202621621 [mm] "26 pins, straight, gold plating"
  rect 1.6x1.6 hole 1.1: 1(-15.24,-1.27)
  round 1.6 hole 1.1: 2(-15.24,1.27) 3(-12.7,-1.27) 4(-12.7,1.27) 5(-10.16,-1.27) 6(-10.16,1.27) 7(-7.62,-1.27) 8(-7.62,1.27) 9(-5.08,-1.27) 10(-5.08,1.27) 11(-2.54,-1.27) 12(-2.54,1.27) 13(0,-1.27) 14(0,1.27) 15(2.54,-1.27) 16(2.54,1.27) 17(5.08,-1.27) 18(5.08,1.27) 19(7.62,-1.27) 20(7.62,1.27) 21(10.16,-1.27) 22(10.16,1.27) 23(12.7,-1.27) 24(12.7,1.27) 25(15.24,-1.27) 26(15.24,1.27)
  silkscreen extent -20.44,-4.5 20.44,4.5, body extent -20.34,-4.42 20.34,4.75, height 9.13
Bead_1210 [mil]
  rect 49x107 smd: 1(-45,0) 2(45,0)
  silkscreen extent -85,-65 85,65, body extent -63,-51 63,51, height 39
CAP2220 [mil]
  rect 70x180 smd: 1(-115,0) 2(115,0)
  silkscreen extent -160,-100 160,100, body extent -160,-100 160,100, height 200
CAP2220_3 [mil]
  rect 70x330 smd: 1(-115,0) 2(115,0)
  silkscreen extent -160,-180 160,180, body extent -160,-180 160,180, height 200
CAP-FILM_EZPE_41X30A [mil]
  round 120 / inner round 130 / far side round 120 hole 59: 1(-740,-200) 1(-740,200) 2(740,-200) 2(740,200)
  silkscreen extent -817,-590 817,590, body extent -815,-591 819,591, height 2008
CT_EE13 [mil]
  rect 90x30 / inner rect 0x0 / far side rect 0x0 all layers, no hole: 1(-370,200) 2(-370,100) 3(-370,0) 4(-370,-100) 5(-370,-200) 6(370,-200) 7(370,-100) 11(370,0) 11(370,100) 11(370,200)
  rect 250x135 / inner rect 0x0 / far side rect 0x0 all layers, no hole: 11(0,240) 12(0,-240)
  silkscreen extent -235,-235 235,235
DIP7 [mm]
  rect 2x1.65 hole 0.85: 1(-4.445,3.81)
  oval 2x1.65 hole 0.85: 2(-4.445,1.27) 3(-4.445,-1.27) 4(-4.445,-3.81) 5(4.445,-3.81) 6(4.445,1.27) 7(4.445,3.81)
  silkscreen extent -3.23,-5.08 3.23,5.08, body extent -4.59,-4.63 4.59,4.63, height 4.22
DO-214AC(SMA) [mm]
  rect 2x2.2 smd: 1(-2.032,0) 2(2.032,0)
  silkscreen extent -2.1,-1.53 2.1,1.53, body extent -2.3,-1.35 2.3,1.35, height 2.4
EE8 [mil]
  round 70 / inner round 110.24 / far side round 70 hole 39: 1(-135,100) 1(135,100) 2(-135,-100) 2(135,-100)
  silkscreen extent -188,-181 187,182, body extent -185,-181 189,181, height 394
Heatsink_80x60x20_with_25mm_FAN [mil]
  round 236.22 / inner round 80 / far side round 236.22 hole 137: 1(-1380,395) 2(1380,395)
  silkscreen extent -1575,-40 1575,1770, body extent -1570,0 1570,1770, height 2350
HOLE3.5-2 [mm]
  round 0 hole 3.5 unplated: 1(0,0)
  silkscreen extent -4.53,-4.58 4.54,4.47, body extent -2.49,-2.87 2.51,2.9
INDUCTOR-7*7*3.5 [mil]
  rect 80x80 smd: 1(-135.75,0) 2(135.75,0)
  silkscreen extent -145,-145 145,145, body extent -144,-144 144,144, height 130
L31_W11_H20_P27.5 [mm] "THT Film Capacitors, body 31x11mm"
  round 2.54 hole 1.1: 1(-13.75,0) 2(13.75,0)
  silkscreen extent -16.25,-6 16.25,6, body extent -15.5,-5.5 15.5,5.5, height 20.05
"LED 5MM-R" [mm] "红色5mm直插LED"
  rect 1.7x1.7 hole 0.9: 1(-1.27,0)
  round 1.7 hole 0.9: 2(1.27,0)
  silkscreen extent -2.8,-2.8 2.33,2.8, body extent -2.85,-2.85 2.45,2.85, height 8.75
Logo [mil] "onsemi"
  silkscreen extent 0,2 1350,236
PIN1 [mm] "Connector; Plug"
  rect 1.5x1.5 hole 0.9: 1(0,0)
  silkscreen extent -1.4,-1.4 1.4,2.17
SC70-5 [mil]
  rect 15x30 smd mask+0: 1(-26,-37.5) 2(0,-37.5) 3(26,-37.5) 4(26,37.5) 5(-26,37.5)
  silkscreen extent -60,-40 60,40, body extent -39,-41 39,41, height 40
SC70-6 [mil]
  rect 15x30 smd mask+0: 1(-26,-37.5) 2(0,-37.5) 3(26,-37.5) 4(26,37.5) 5(0,37.5) 6(-26,37.5)
  silkscreen extent -60,-40 60,40, body extent -39,-41 39,41, height 40
SMT_0805_CM [mil]
  rect 50x45 smd: 1(-45,0) 2(45,0)
  silkscreen extent -93,-40 93,40, body extent -39,-24 39,24, height 26
SMT_0805_RM [mil]
  rect 50x45 smd: 1(-45,0) 2(45,0)
  silkscreen extent -90,-40 90,40, body extent -39,-25 39,25, height 22
SMT_1206_CM [mil]
  rect 60x60 smd: 1(-65,0) 2(65,0)
  silkscreen extent -120,-50 120,50, body extent -63,-31 63,31, height 30
SMT_1206_RM [mil]
  rect 60x60 smd: 1(-65,0) 2(65,0)
  silkscreen extent -115,-50 115,50, body extent -63,-31 63,31, height 24
SMT_1210 [mil]
  rect 60x100 smd: 1(-65,0) 2(65,0)
  silkscreen extent -121,-70 121,70, body extent -63,-31 63,31, height 30
SMT_2512_R [mil]
  rect 60x125 smd: 1(0,0) 2(-251.97,0)
  silkscreen extent -302,-85 50,85, body extent -260,-65 8,65, height 25
SOD-123FL [mil]
  rect 65x60 smd: 1(70,0) 2(-70,0)
  silkscreen extent -90,-50 53,50, body extent -73,-31 73,31, height 47
SOD-323M [mil]
  rect 45x45 smd: 1(0,0) 2(90,0)
  silkscreen extent -33,-31 140,31, body extent 2,-24 100,26, height 35
SOIC8E [mm]
  oval 1.55x0.6 smd: 1(-2.7,1.905) 2(-2.7,0.635) 3(-2.7,-0.635) 4(-2.7,-1.905) 5(2.7,-1.905) 6(2.7,-0.635) 7(2.7,0.635) 8(2.7,1.905)
  rect 2.62x3.51 smd: 9(0,0)
  silkscreen extent -3.32,-2.45 1.6,2.87, body extent -3,-2.45 3,2.45, height 1.6
Sop8 [mm]
  oval 1.55x0.6 smd: 1(-2.7,1.905) 2(-2.7,-1.905) 2(-2.7,-0.635) 2(-2.7,0.635) 2(2.7,-1.905) 2(2.7,-0.635) 2(2.7,0.635) 8(2.7,1.905)
  silkscreen extent -3.32,-2.45 1.6,2.87, body extent -3,-2.45 3,2.45, height 1.6
SOP14 [mm]
  oval 1.55x0.6 smd: 1(-2.7,4.445) 2(-2.7,3.175) 3(-2.7,1.905) 4(-2.7,0.635) 5(-2.7,-0.635) 6(-2.7,-1.905) 7(-2.7,-3.175) 8(2.7,-3.175) 9(2.7,-1.905) 10(2.7,-0.635) 11(2.7,0.635) 12(2.7,1.905) 13(2.7,3.175) 14(2.7,4.445)
  silkscreen extent -3.32,-3.68 1.6,5.37, body extent -3,-5 3,5, height 1.6
SOP16W [mil]
  oval 87x23.62 smd: 1(-180,175) 2(-180,125) 3(-180,75) 4(-180,25) 5(-180,-25) 6(-180,-75) 7(-180,-125) 8(-180,-175) 9(180,-175) 10(180,-125) 11(180,-75) 12(180,-25) 13(180,25) 14(180,75) 15(180,125) 16(180,175)
  silkscreen extent -185,-195 125,215, body extent -118,-197 118,197, height 63
SOT-23-3L [mm]
  rect 1.1x0.6 smd: 1(-1.3,0.95) 2(-1.3,-0.95) 3(1.3,0)
  silkscreen extent -1.72,-1.45 0.43,1.87, body extent -1.4,-1.45 1.4,1.45, height 1.2
SOT-23-5L [mm]
  rect 1.1x0.6 smd: 1(-1.3,0.95) 2(-1.3,0) 3(-1.3,-0.95) 4(1.3,-0.95) 5(1.3,0.95)
  silkscreen extent -1.72,-1.45 0.43,1.88, body extent -1.4,-1.45 1.4,1.45, height 1.2
SOT-223 [mm]
  rect 1.9x0.95 smd: 1(-2.95,2.3) 2(-2.95,0) 3(-2.95,-2.3)
  rect 1.9x3.2 smd: 4(2.95,0)
  silkscreen extent -3.78,-3.15 1.68,3.42, body extent -3.43,-3.25 3.53,3.25, height 1.7
SSOP8 [mil]
  rect 60x11.8 smd: 1(-70,30) 2(-70,10) 3(-70,-10) 4(-70,-30) 5(70,-30) 6(70,-10) 7(70,10) 8(70,30)
  silkscreen extent -60,-50 30,80, body extent -118,-98 118,98, height 49
TermL [mil]
  round 150 / inner round 60 / far side round 150 hole 79: 1(-100,150) 1(-100,-150) 1(100,150) 1(100,-150)
  silkscreen extent -175,-180 175,180, body extent -173,-175 173,175, height 244
TO92a [mil]
  round 70 hole 32: 1(-100,50) 2(0,-50) 3(100,50)
  silkscreen extent -140,-50 140,140, body extent -112,-50 112,100, height 269
TO247#1 [mil]
  oval 100x150 hole 62: 1(-215,0) 2(0,0) 3(215,0)
  silkscreen extent -310,-105 315,105, body extent -305,-98 305,98, height 984
TO247#2 [mil]
  oval 100x150 hole 62: 1(-215,0) 2(0,0)
  oval 100x180 hole 62: 3(215,0)
  silkscreen extent -310,-105 315,105, body extent -305,-98 305,98, height 984
TO247#3 [mil]
  oval 100x160 hole 62: 1(-215,0)
  oval 100x150 hole 62: 2(0,0) 3(215,0)
  silkscreen extent -310,-105 315,105, body extent -305,-98 305,98, height 984
TO247#4 [mil]
  oval 100x180 hole 62: 1(-215,0) 3(215,0)
  oval 100x150 hole 62: 2(0,0)
  silkscreen extent -310,-105 315,105, body extent -305,-98 305,98, height 984
Trans_EE13_6_6_10Pin_V#1 [mm]
  round 2 hole 1.2: 1(-4.255,-5) 1(-4.255,-2.5) 1(-4.255,0) 1(-4.255,2.5) 2(4.255,-5) 2(4.255,-2.5) 2(4.255,0) 2(4.255,2.5) 2(4.255,5)
  rect 2x2 hole 1.2: 1(-4.255,5)
  silkscreen extent -8.6,-7.5 7.5,7.5, body extent -6.91,-6.8 6.91,6.83, height 14.24
Trans_EE13_6_6_10Pin_V#2 [mm]
  rect 0x0 all layers, no hole: 1(-4.255,5)
  round 2 hole 1.2: 2(-4.255,2.5) 3(-4.255,0) 4(-4.255,-2.5) 6(4.255,-5) 7(4.255,-2.5) 9(4.255,2.5) 10(4.255,5)
  round 0 all layers, no hole: 5(-4.255,-5) 8(4.255,0)
  silkscreen extent -8.6,-7.5 7.5,7.5, body extent -6.91,-6.8 6.91,6.83, height 14.24
Trans_PQ2016_14P#1 [mil]
  round 70 / inner round 110.24 / far side round 70 hole 39: 1(-400,395) 4(-400,100) 7(-400,-295) 8(-400,-395) 9(400,-400) 10(400,-250) 11(400,-100) 13(400,250)
  round 0 all layers, no hole: 2(-400,295) 3(-400,195) 5(-400,-100) 6(-400,-195) 12(400,100) 14(400,400)
  silkscreen extent -543,-471 543,471, body extent -493,-437 493,437, height 642
Trans_PQ2016_14P#2 [mil]
  round 70 / inner round 110.24 / far side round 70 hole 39: 1(-400,395) 3(-400,195) 5(-400,-100) 6(-400,-195) 7(-400,-295) 8(-400,-395) 9(400,-400) 10(400,-250) 11(400,-100) 12(400,100) 13(400,250) 14(400,400)
  round 0 all layers, no hole: 2(-400,295) 4(-400,100)
  silkscreen extent -543,-471 543,471, body extent -493,-437 493,437, height 642
WCAP-AI3H_35x57 [mm] "Aluminium Electrolytic Snap-In Capacitors, Ф35x57mm"
  rect 3.81x3.81 hole 2: 1(5,0)
  round 3.81 hole 2: 2(-5,0)
  silkscreen extent -17.5,-17.5 17.5,17.5, body extent -24.73,-24.69 24.62,24.66, height 57.09
WCAP-ATG5_10x25 [mm] "Aluminum Electrolytic Capacitors, 10x25mm"
  round 1.4 hole 0.9: 1(-2.5,0) 2(2.5,0)
  silkscreen extent -5.25,-5.25 5.25,5.25, body extent -4.99,-5 5,5, height 25.31
WE-TI_1014_Standard [mm] "Radial Leaded Wire Wound Inductor, body diameter 10.5mm"
  rect 1.8x1.8 hole 1.2: 1(-2.5,0)
  round 1.8 hole 1.2: 2(2.5,0)
  silkscreen extent -5.25,-5.25 5.25,5.25, body extent -5,-5 5,5, height 14.1
XH-4A [mm]
  rect 1.8x2.5 hole 1: 1(0,0)
  oval 1.8x2.5 hole 1: 2(2.54,0) 3(5.08,0) 4(7.62,0)
  silkscreen extent -2.45,-3.4 9.95,2.35, body extent -2.45,-3.4 9.95,2.35, height 7

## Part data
C1 C10: library part 890493427007CS, "WCAP-FTBE THT Film Capacitors, 470nF, 1000VDC", Capacitance=470nF, Insulation Resistance="3000Ohm x F", Operating Temperature="-40 to +85degC", Rated Voltage=1000VDC, Rate of Voltage Rise=22V/us
C2 C3: library part "CAP POL"
C5 C20 C23 C30 C33 C40 C43 C50 C53 C60 C61 C63 C67 C68 C69 C70 C74 C75 C76 C77 C79 C80 C86 C87 C90 C92 C99 C100 C102 C110 C114 C115 C116 C120 C123 C128 C129 C130 C133 C140 C143 C148 C150 C153 C214 C229 C260 C261: library part "CAP NP"
C6: library part "CAP NP", "EZPE80306MTA"
C7 C8 C11 C12 C22 C24 C25 C26 C27 C32 C34 C35 C36 C37 C42 C44 C45 C46 C47 C52 C54 C55 C56 C57 C62 C64 C65 C66 C72 C73 C85 C88 C91 C93 C111 C112 C113 C122 C124 C125 C126 C127 C132 C134 C135 C136 C137 C142 C144 C145 C146 C147 C152 C154 C155 C156 C157 C160 C161 C162 C163 C164 C169 C170 C180 C181 C182 C183 C184 C194 C201 C202 C203 C204 C205 C206 C208 C209 C210 C212 C217 C239 C240: library part CAP_0805
C21 C31 C41 C51 C121 C131 C141 C151: library part CAP_1206
C98: library part 860021375012, "WCAP-ATG5 THT Aluminum Electrolytic Capacitors, D10mm x L25mm, 22uF, +/-20%, 400VDC", Capacitance=22uF, Capacitance Tolerance=+/-20%, Leakage Current=264uA, Operating Temperature="-25 to +105degC", Rated Voltage=400VDC, Ripple Current max.=162mA
"Control Interface": "Male Box Header WR-BHD, THT, Vertical, pitch 2.54 mm, 26 pins", Contact Resistance="20 mOhm", Operating Temperature="-40 to 125 degC", Withstanding Voltage="500 VAC", Working Voltage="250 VAC"
CT10 CT20: library part "Trans Cupl", "Transformer (Coupled Inductor Model)"
D20 D30 D40 D50 D120 D130 D140 D150: library part D_SMA(DO-214AC)
D60 D63 D66 D70 D71 D73 D74 D75 D76 D78 D80 D86 D90 D91 D99 D100 D102 D110 D111 D191 D192 D194: library part DIODE
D77 D79 D81 D101 D103: library part "DIODE ZENER"
D211: library part BAT54S/SOT
FAN1 FAN2: library part "Header 4", "Header, 4-Pin"
Fault Power: library part LED
L90: library part 7447480222, "Radial Leaded Wire Wound Inductor WE-TI, size 1014, 2200 uH, 0.48 A", DC Resistance max.="2.5 Ohm", Inductance="2200 uH", Operating Temperature="-40 to 125 degC", Rated Current="0.48 A", Saturation Current="0.56 A", Self Resonant Frequency="0.83 MHz"
L110 L190: library part "INDUCTOR IRON"
Q20 Q30 Q40 Q50 Q120 Q130 Q140 Q150: library part SICMOS
Q81: library part "MOSFET N"
Q160 Q201: library part Q_PNP_SOT-23-3L
Q200: library part "NPN BCE"
R4 R5 R6 R10 R11 R12 R13 R14 R15 R16 R21 R22 R25 R27 R31 R32 R35 R39 R41 R42 R45 R47 R51 R52 R55 R59 R60 R61 R62 R63 R64 R65 R66 R68 R70 R71 R72 R73 R74 R75 R76 R77 R78 R79 R80 R81 R84 R86 R87 R88 R89 R91 R92 R93 R94 R95 R96 R97 R98 R100 R101 R102 R103 R105 R106 R110 R111 R112 R113 R121 R122 R125 R127 R131 R132 R135 R139 R141 R142 R145 R147 R151 R152 R155 R159 R160 R161 R162 R163 R164 R165 R166 R167 R168 R169 R171 R172 R180 R181 R182 R183 R184 R190 R193 R194 R195 R196 R197 R209 R210 R211 R213 R217 R230 R231 R232 R240 R250 R251 R252 R260 R261 R262: library part R
R20 R23 R24 R26 R30 R33 R34 R36 R37 R38 R40 R43 R44 R46 R50 R53 R54 R56 R57 R58 R67 R82 R83 R85 R90 R120 R123 R124 R126 R130 R133 R134 R136 R137 R138 R140 R143 R144 R146 R150 R153 R154 R156 R157 R158 R177 R178 R187 R188 R189 R200 R202 R203 R205 R207 R208 R212 R219: library part R_0805
T41: library part TRAN_HM31
T41+ T41-: library part Plug, "Plug"
T60: library part Transformer_3_Winding
T70: library part Transformer_5_winding
T71 T72: library part Transformer_Pulse_1_to_2
TransAA TransAB TransUA TransUB VBAT+ VBAT- VBUS+ VBUS-: library part P_1
U4 U81 U82 U181 U211: library part TL431
U6: library part NCV210
U20 U30 U40 U50 U120 U130 U140 U150: library part U_NCV57000_SO-16
U60 U70: library part FSL538
U90: library part FSL4110
U91: library part LM383/TO220_1
U92: library part LDO_SC70-5
U93: library part LDO_SOT223
U110: library part NCV890200
U160: library part LM339
U180: library part NCD98010

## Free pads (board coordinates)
  round 60 hole 30: 3(2835,4465) 4(2525,3575) 5(2600,3575) 6(2675,3575) 7(1175,3450) 7(1175,3525) 7(1175,3600) 7(1175,3675) 7(1250,3450) 7(1250,3525) 7(1250,3600) 7(1250,3675) 7(1325,3450) 7(1325,3525) 7(1325,3600) 7(1325,3675) 7(1400,3450) 7(1400,3525) 7(1400,3600) 7(1400,3675) 7(1475,3450) 7(1475,3525) 7(1475,3600) 7(1475,3675) 7(1550,3450) 7(1550,3525) 7(1550,3600) 7(1550,3675) 7(2225,3575) 7(2225,3650) 7(2225,3725) 7(2300,3575) 7(2300,3650) 7(2300,3725) 7(2375,3575) 7(2375,3650) 7(2375,3725) 7(2450,3575) 7(2450,3650) 7(2450,3725) 7(2525,3650) 7(2525,3725) 7(2600,3650) 7(2600,3725) 7(2675,3650) 7(2675,3725) 7(2750,3575) 7(2750,3650) 7(2750,3725) 8(3100,2875) 8(3100,2950) 8(3100,3025) 8(3175,2875) 8(3175,2950) 8(3175,3025) 8(3175,3100) 8(3250,2875) 8(3250,2950) 8(3250,3025) 8(3250,3100) 8(3250,3175) 8(3250,3250) 8(3325,2875) 8(3325,2950) 8(3325,3025) 8(3325,3100) 8(3325,3175) 8(3325,3250) 8(3400,2950) 8(3400,3025) 8(3400,3100) 8(3400,3175) 8(3400,3250) 8(5215,1950) 10(1650,6450) 11(1650,6525) 12(1650,6600) 13(1650,6300) 13(1650,6375) 13(1725,6150) 13(1725,6225) 13(1725,6300) 13(1725,6375) 13(1800,6150) 13(1800,6225) 13(1800,6300) 13(1875,6225) 13(1875,6300) 14(1725,6450) 15(1725,6525) 16(1725,6600) 17(1725,6675) 18(1800,6375) 19(1800,6450) 20(1800,6525) 21(1800,6600) 22(1800,6675) 28(1875,6600) 29(1875,6750) 30(1875,6675) 31(1875,6375) 32(1875,6525) 33(2125,6700) 34(2125,6600) 35(1875,6450) 36(1775,7200) 36(1775,7275) 36(1800,6750) 37(7175,7260) 38(7110,7260) 39(7240,7260) 40(7110,7400) 41(7175,7400) 42(7240,7400) 43(9450,7225) 44(9225,7225) 45(9300,7225) 46(9375,7225) 47(8675,7700) 47(8675,7775) 47(8675,7850) 47(8675,7925) 47(8750,7700) 47(8750,7775) 47(8750,7850) 47(8750,7925) 47(8825,7700) 47(8825,7775) 47(8900,7700) 47(8900,7775) 47(8975,7775) 47(9225,7300) 48(9300,7300) 49(9375,7300) 50(9275,6850) 51(9275,6550) 51(9275,6625) 51(9350,6325) 51(9350,6400) 51(9350,6475) 51(9350,6550) 51(9350,6625) 52(9275,6775) 53(9350,6775) 54(9275,6700) 55(9350,6700) 57(7400,3550) 58(7400,3640) 59(7400,3725)
  round 120 hole 59: 56(8450,2420) 56(8450,3900) 56(9250,2420) 56(9250,3900)
  round 180 hole 100: 61(4700,7500) CT20A(4700,7800)

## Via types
v1: diameter 25, hole 12, Top Layer to Bottom Layer, 169 vias
v2: diameter 50, hole 28, Top Layer to Bottom Layer, 31 vias

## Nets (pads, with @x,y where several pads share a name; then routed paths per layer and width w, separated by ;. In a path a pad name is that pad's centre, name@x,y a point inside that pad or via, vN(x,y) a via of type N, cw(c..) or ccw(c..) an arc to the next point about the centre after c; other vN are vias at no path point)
+3.3VBA: C114.2 C163.2 D194.2 D211.2 L110.2 Q160.2 R25.1 R35.1 R45.1 R55.1 R113.1 R125.1 R135.1 R145.1 R155.1 R166.1 R171.1 R177.2 R178.1 R207.2 | length 15152.3
  Top Layer w23: v1(2490,5485) v1(3185,5485) v1(3880,5485) v1(4575,5485) 4585,5495 6200,5495 v1(6265,5560) v1(6875,5560) v1(7535,5560) v1(8195,5560) v1(8855,5560) ; v1(7605,1635) v1(7605,2220)
  Top Layer w25: v1(5500,2450) v1(5500,2875)
  Top Layer w60: v2(6760,4245) v2(6760,2995) 7130,2995 7225,2900 v2(7225,2325)
  Bottom Layer w12: v1(2490,5485) v1@2490,5490
  Bottom Layer w23: D211.2@7477.4,1586.18 7526.22,1635 v1(7605,1635)
  Bottom Layer w45: R35.1@2490,5455 v1(2490,5485) ; R207.2@5430,2450 v1(5500,2450) ; v1(6265,5560) C163.2@6265,5435 R166.1@6265,5340 6265,5210 6475,5000 6500,5000 6925,4575 6925,4325 6845,4245 v2(6760,4245) ; R113.1@6670,4705 6810.75,4564.25 L110.2@6810.75,4475
  Bottom Layer w50: v2(7225,2325) 7330,2220 v1(7605,2220) R177.2@7800,2220 R178.1@8300,2220
  Bottom Layer w60: v1(5500,2875) 6355,2875 ; R171.1@6355,2445 6355,2875 ; C114.2@6737.5,4267.5 6810.75,4340.75 L110.2@6810.75,4475 ; v2(6760,2995) 6375,2995 D194.2@6355,2975 6355,2875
